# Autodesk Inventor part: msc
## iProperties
Shininess: 64.0
Length Units: 11269
Angle Units: 11279
Time Units: 11290
Mass Units: 11283
Length Display Precision: 3
Angle Display Precision: 2
Compacted: True
Part Number: msc
Document SubType Name: Modeling
Created: 2004-07
Designer: Peter
Manufacturer: Standard
Standards Organization: Custom
Density: 0.0
Volumn: 0.0
Area: 0.0
PropertySet Name: Model Information
Control State: 0
Master: False
Checked Out: False
Author: Peter
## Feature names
1. Revolution1
